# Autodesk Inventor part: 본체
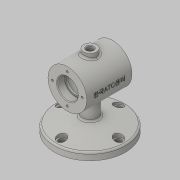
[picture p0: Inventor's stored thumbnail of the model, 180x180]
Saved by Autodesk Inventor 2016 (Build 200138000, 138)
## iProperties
Created: 2018-12
Part Number: 본체
Material: Generic
Document SubType Name: Modeling
Designer: Administrator
Density: 1 g/cm^3
Appearance: Default
Mass: 245.081 g
Surface Area: 551.221 cm^2
Volume: 245.081 cm^3
Author: Administrator
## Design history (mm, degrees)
sketch "스케치1"
  geometry: C1 r 55 at (0, 0); 1 further point
  constraints: 1 centre point, 1 coincident
  dimensions: "d0" = 110 diameter of C1
extrude "돌출1" new body sketch "스케치1" distance "d1" = 11; taper "d2" = 0 deg
sketch "스케치3"
  geometry: C1 r 12 at (0, 0); 1 further point
  constraints: 1 centre point, 1 coincident
  dimensions: "d3" = 24 diameter of C1
extrude "돌출2" join sketch "스케치3" distance "d4" = 64; taper "d5" = 0 deg
sketch "스케치4"
  geometry: L1 (11, -55)-(11, 55) reference; L2 (11, 55)-(22.522, 12); L3 (11, 12)-(75, 12) reference; L4 (22.522, 12)-(22.522, 0); L5 (11, -12)-(75, -12) reference; L6 (22.522, 0)-(11, 0); L7 (0, 55)-(11, 55) reference; 1 further point
  constraints: 6 end point, 1 midpoint, 1 perpendicular, 1 point on line
  dimensions: "d6" = 75 deg angle of L7 L2; "d7" = 11.52182 distance between parallel lines of L4 L1 (derived); "d8" = 24 diameter of L2.end L6
revolve "회전1" sketch "스케치4" stored, may be unused: angle "d9" = 90 deg
sketch "스케치5"
  geometry: L1 (12, 75)-(-12, 75) reference; C1 r 30 at (0, 75); 1 further point
  constraints: 1 centre point, 1 midpoint
  dimensions: "d10" = 60 diameter of C1
extrude "돌출3" join sketch "스케치5" stored distance "d11" = 70; taper "d12" = 0 deg
node "작업 평면1"
sketch "스케치6"
  geometry: C1 r 10 at (0, 0); 1 further point
  constraints: 1 centre point, 1 coincident
  dimensions: "d14" = 20 diameter of C1
extrude "돌출4" join sketch "스케치6" stored distance "d15" = 70; taper "d16" = 0 deg
hole "구멍1" diameter "d19" = 32; stored, may be unused: countersink angle "d23" = 90 deg, drill point angle "d25" = 0 deg; dims "d17" = 10, "d18" = 10, "d20" = 6, "d21" = 4, "d22" = 2, "d24" = 12
hole "구멍2" diameter "d28" = 28; stored, may be unused: countersink angle "d32" = 90 deg, drill point angle "d34" = 0 deg; dims "d26" = 10, "d27" = 10, "d29" = 6, "d30" = 4, "d31" = 2, "d33" = 3
hole "구멍3" diameter "d37" = 50; stored, may be unused: countersink angle "d41" = 90 deg, drill point angle "d43" = 0 deg; dims "d35" = 10, "d36" = 10, "d38" = 6, "d39" = 4, "d40" = 2, "d42" = 40
hole "구멍4" diameter "d46" = 28; stored, may be unused: countersink angle "d50" = 90 deg, drill point angle "d52" = 0 deg; dims "d44" = 10, "d45" = 10, "d47" = 6, "d48" = 4, "d49" = 2, "d51" = 3
hole "구멍5" diameter "d55" = 32; stored, may be unused: countersink angle "d59" = 90 deg, drill point angle "d61" = 0 deg; dims "d53" = 10, "d54" = 10, "d56" = 6, "d57" = 4, "d58" = 2, "d60" = 12
hole "구멍6" diameter "d64" = 10; stored, may be unused: countersink angle "d68" = 90 deg, drill point angle "d70" = 0 deg; dims "d62" = 10, "d63" = 10, "d65" = 6, "d66" = 4, "d67" = 2, "d69" = 20
sketch "스케치7" dims "d71" = 46
  geometry: 3 further points
  constraints: 1 vertical alignment, 2 other
hole "구멍7" sketch "스케치7" at (0, 23) diameter "d72" = 3.242; stored, may be unused: countersink angle "d76" = 90 deg, drill point angle "d78" = 118 deg; dims "d73" = 8, "d74" = 4, "d75" = 2, "d77" = 10
node "작업 평면2"
sketch "스케치8" dims "d83" = 88
  geometry: C1 r 4.5 at (44, 0); 2 further points
  constraints: 1 centre point, 1 coincident, 1 horizontal alignment, 2 other
  dimensions: "d84" = 9 diameter of C1
extrude "돌출5" cut sketch "스케치8" stored distance "d85" = 70; taper "d86" = 0 deg
sketch "스케치9"
  geometry: C1 r 4.5 at (44, 0) reference; C2 r 7 at (44, 0); 1 further point
  constraints: 1 centre point, 1 coincident
  dimensions: "d87" = 14 diameter of C2
extrude "돌출6" cut sketch "스케치9" distance "d88" = 70; taper "d89" = 0 deg
fillet "모깎기1" dims "d93" = 3
fillet "모깎기2" dims "d94" = 3
chamfer "모따기1" distance "d95" = 1; stored, may be unused: second distance "d96" = 2, angle "d97" = 45 deg
fillet "모깎기3" dims "d98" = 0.3
node "작업 평면3"
sketch "스케치10"
  geometry: L1 (30, -35)-(30, 35) reference; L2 (30, 35)-(-30, 35) reference; 2 further points
  constraints: 1 other
  dimensions: "d99" = 30 distance from line of point (0, 0) L1; "d100" = 35 distance from line of L2 point (0, 0)
feature "엠보싱1" sketch "스케치10" dims "d101" = 0.5, "d102" = 0
node "솔리드1"
pattern_circular "원형 패턴1" dims angle "d80" = 360 deg
mirror "대칭1"
pattern_circular "원형 패턴2" dims angle "d91" = 360 deg
other parameters: "d13" = 112
